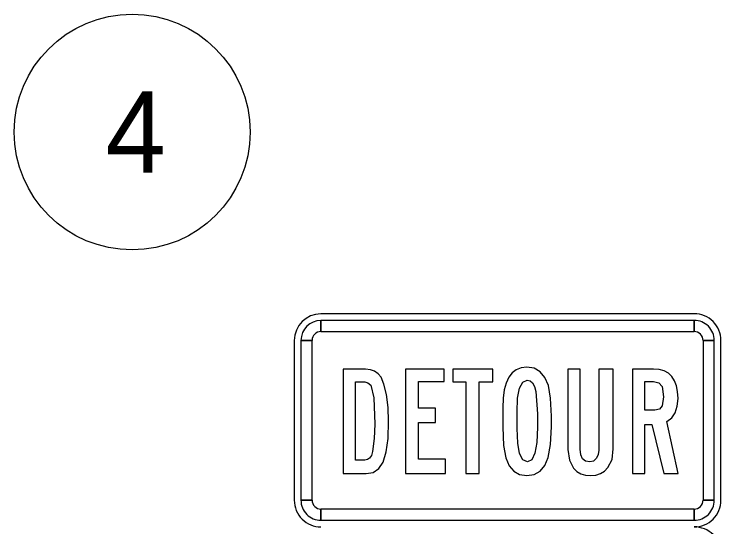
# Model space of a CAD drawing. Extents: x 10133 to 81668, y 5524 to 11018.
# Drawn here: x 25396.3 to 25562, y 9582.4 to 9702.8 of the extents above; entities that cross this region are included whole.
import ezdxf

# ---------------------------------------------------------------- set-up
doc = ezdxf.new("R2010")
doc.units = 0
for name, color, linetype in [('DisAdjoinersText', 7, 'Continuous'), ('DisPropROW', 7, 'Continuous'), ('trf_SignNumber_Text', 7, 'Continuous')]:
    doc.layers.add(name, color=color, linetype=linetype)

msp = doc.modelspace()

# ---------------------------------------------------------------- linework, layer by layer
at = {"layer": 'DisAdjoinersText'}
msp.add_arc((25555.73, 9576.19), 6.25, 360, 90.0002, dxfattribs=at)
at = {"layer": 'DisPropROW'}
for p, q in [((25555.73, 9632.44), (25468.23, 9632.44)), ((25468.23, 9628.27), (25468.23, 9630.85)), ((25555.73, 9630.85), (25555.73, 9628.27)), ((25461.98, 9626.19), (25461.98, 9588.69)), ((25463.54, 9626.19), (25466.14, 9626.19)), ((25557.81, 9626.19), (25560.42, 9626.19)), ((25561.98, 9588.69), (25561.98, 9626.19)), ((25466.14, 9588.69), (25463.54, 9588.69)), ((25560.42, 9588.69), (25557.81, 9588.69)), ((25468.23, 9584.02), (25468.23, 9586.6)), ((25555.73, 9586.6), (25555.73, 9584.02))]:
    msp.add_line(p, q, dxfattribs=at)
for points in [[(25555.73, 9630.85), (25468.23, 9630.85), (25468.23, 9628.27), (25555.73, 9628.27), (25555.73, 9630.85)], [(25463.54, 9626.19), (25463.54, 9588.69), (25466.14, 9588.69), (25466.14, 9626.19), (25463.54, 9626.19)], [(25560.42, 9588.69), (25560.42, 9626.19), (25557.81, 9626.19), (25557.81, 9588.69), (25560.42, 9588.69)], [(25488.02, 9594.94), (25497.42, 9594.94), (25497.42, 9598.3), (25491.06, 9598.3), (25491.06, 9606.95), (25495.07, 9606.95), (25495.07, 9610.32), (25491.06, 9610.32), (25491.06, 9616.57), (25497.08, 9616.57), (25497.08, 9619.45), (25488.02, 9619.45)], [(25499.13, 9619.45), (25499.13, 9616.45), (25502.17, 9616.45), (25502.17, 9594.94), (25505.33, 9594.94), (25505.33, 9616.45), (25508.52, 9616.45), (25508.52, 9619.45)], [(25526.14, 9619.45), (25526.14, 9600.57), (25526.46, 9598.13), (25527.41, 9596.25), (25528.18, 9595.46), (25529.12, 9594.9), (25530.21, 9594.56), (25531.46, 9594.46), (25532.69, 9594.57), (25533.77, 9594.93), (25534.71, 9595.51), (25535.51, 9596.35), (25536.46, 9598.27), (25536.77, 9600.72), (25536.77, 9619.45), (25533.36, 9619.45), (25533.36, 9600.42), (25533.23, 9599.4), (25532.85, 9598.55), (25532.15, 9597.89), (25531.24, 9597.68), (25530.27, 9597.86), (25529.58, 9598.42), (25529.16, 9599.35), (25529.03, 9600.67), (25529.03, 9619.45)], [(25468.23, 9584.02), (25555.73, 9584.02), (25555.73, 9586.6), (25468.23, 9586.6), (25468.23, 9584.02)]]:
    msp.add_lwpolyline(points, close=True, dxfattribs=at)
for points in [[(25473.47, 9594.94), (25478.81, 9594.94), (25480.47, 9595.23), (25481.82, 9596.11), (25482.81, 9597.65), (25483.52, 9600.02), (25483.95, 9603.21), (25484.09, 9607.22), (25483.96, 9610.45), (25483.58, 9613.47), (25483, 9615.94), (25482.31, 9617.57), (25481.64, 9618.39), (25480.81, 9618.98), (25479.82, 9619.33), (25478.68, 9619.45), (25473.47, 9619.45), (25473.47, 9594.94)], [(25522.26, 9608.44), (25522.08, 9612.67), (25521.54, 9615.64), (25520.74, 9617.52), (25519.63, 9618.86), (25518.22, 9619.66), (25516.52, 9619.94), (25515.18, 9619.78), (25514.02, 9619.33), (25513.05, 9618.58), (25512.25, 9617.55), (25511.62, 9616.19), (25511.18, 9614.56), (25510.91, 9612.62), (25510.83, 9610.39), (25510.88, 9608.91), (25510.88, 9605.8), (25511.06, 9601.56), (25511.57, 9598.62), (25512.34, 9596.79), (25513.42, 9595.49), (25514.81, 9594.71), (25516.52, 9594.46), (25518.2, 9594.72), (25519.59, 9595.51), (25520.69, 9596.83), (25521.49, 9598.7), (25522.06, 9601.75), (25522.26, 9605.95), (25522.26, 9608.44)], [(25551.93, 9612.57), (25551.84, 9614.17), (25551.57, 9615.57), (25551.12, 9616.75), (25550.49, 9617.73), (25549.68, 9618.48), (25548.69, 9619.02), (25547.51, 9619.34), (25546.17, 9619.45), (25541.3, 9619.45), (25541.3, 9594.94), (25544.19, 9594.94), (25544.19, 9606.46), (25545.8, 9606.46), (25548.61, 9594.94), (25551.93, 9594.94), (25549.34, 9607.14), (25550.47, 9608.03), (25551.28, 9609.23), (25551.76, 9610.74), (25551.93, 9612.57)], [(25476.35, 9598.1), (25476.35, 9616.45), (25478.49, 9616.45), (25479.25, 9616.25), (25479.9, 9615.68), (25480.62, 9612.75), (25480.86, 9606.56), (25480.68, 9603.14), (25480.34, 9600.1), (25480.05, 9599.22), (25479.64, 9598.59), (25479.12, 9598.22), (25478.5, 9598.1), (25476.35, 9598.1)], [(25518.98, 9609), (25519, 9605.81), (25518.85, 9602.24), (25518.4, 9599.71), (25517.66, 9598.18), (25516.62, 9597.68), (25515.56, 9598.16), (25514.8, 9599.64), (25514.35, 9602.09), (25514.2, 9605.54), (25514.2, 9609.37), (25514.34, 9612.67), (25514.78, 9615.02), (25515.52, 9616.43), (25516.55, 9616.89), (25517.25, 9616.72), (25517.82, 9616.22), (25518.27, 9615.37), (25518.6, 9614.2), (25518.98, 9609)], [(25548.51, 9612.95), (25548.22, 9610.84), (25547.57, 9610.08), (25546.53, 9609.84), (25544.19, 9609.84), (25544.19, 9616.57), (25546.21, 9616.57), (25547.42, 9616.28), (25548.18, 9615.4), (25548.51, 9612.95)]]:
    msp.add_lwpolyline(points, dxfattribs=at)
for centre, radius, start, end in [((25468.23, 9626.19), 6.25, 90.0002, 179.9998), ((25555.73, 9626.19), 6.25, 0, 90.0002), ((25468.23, 9626.19), 4.69, 90.0002, 179.9998), ((25555.73, 9626.19), 4.69, 0, 90.0002), ((25468.23, 9626.19), 2.08, 90.0002, 179.9998), ((25555.73, 9626.19), 2.08, 0, 90.0002), ((25468.23, 9588.69), 6.25, 179.9998, 270.0001), ((25468.23, 9588.69), 4.69, 179.9998, 270.0001), ((25468.23, 9588.69), 2.08, 179.9998, 270.0001), ((25555.73, 9588.69), 6.25, 270.0001, 0.0003), ((25555.73, 9588.69), 4.69, 270.0001, 0.0003), ((25555.73, 9588.69), 2.08, 270.0001, 0.0003)]:
    msp.add_arc(centre, radius, start, end, dxfattribs=at)
at = {"layer": 'trf_SignNumber_Text'}
msp.add_circle((25423.98, 9675.1), 27.67, dxfattribs=at)

# ---------------------------------------------------------------- texts
msp.add_text('4', height=19.02, dxfattribs=at).set_placement((25417.76, 9665.6))

doc.saveas('drawing.dxf')
